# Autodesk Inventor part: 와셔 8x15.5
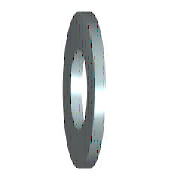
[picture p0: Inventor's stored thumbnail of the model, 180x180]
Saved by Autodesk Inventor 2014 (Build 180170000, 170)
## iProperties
Created: 2012-02
Part Number: 와셔 8x15.5
Material: 강철, 연강
Description: 평면 와셔
Document SubType Name: Modeling
Standard: KS B 1326
Designer: mduedu
Standards Organization: KS
Language: ko-KR
Size Designation: 8x15.5
Categories: <MemberInstance><Categories><Category DisplayName="조임쇠" InternalName="e4da775c-781d-43d5-af7c-5136215cf5a6" Mnemonic="FSTN"><Category DisplayName="와셔" InternalN
Density: 7.86 g/cm^3
Mass: 1.67606 g
Surface Area: 3.86683 cm^2
Volume: 0.213239 cm^3
Appearance: 노란색
IsCustomPart: 1
Author: mduedu
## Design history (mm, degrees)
sketch "스케치"
  geometry: C1 r 7.75 at (0, 0); C2 r 4.2 at (0, 0); 1 further point
  constraints: 2 centre point, 2 coincident
  dimensions: "d0" = 8.4 diameter of C2 (= SD1); "d1" = 15.5 diameter of C1 (= SD2)
extrude "본체" new body sketch "스케치" distance "d2" = 1.6 (= SD); taper "d3" = 0 deg
workaxis "Work Axis1"
workplane "Work Plane1"
body "Solid1"
other parameters: "SD1" = 8.4 [user parameter; used in 1 equation term], "SD2" = 15.5 [user parameter; used in 1 equation term], "SD" = 1.6 [user parameter; used in 1 equation term], "d4" = 0, "d5" = 0, "d6" = 0, "d7" = 0, "NND" = 8 [user parameter]
